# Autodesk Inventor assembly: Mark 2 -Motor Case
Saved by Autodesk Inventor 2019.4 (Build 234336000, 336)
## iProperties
Created: 2020-06
Part Number: Mark 2 -Motor Case
Document SubType Name: Assembly
Designer: Administrator
Title: Mark 2 -Motor Case v6
Author: Administrator
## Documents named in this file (5)
- c:\worker\convert-fusion-r04\tmp\job-1\983\output\files\42c61335-c52f-4d6a-bf4c-243a0625ae02\e151aba5-5efe-49e8-a742-b3bab9d02d3a.iam
- c:\worker\convert-fusion-r04\tmp\job-1\983\output\files\42c61335-c52f-4d6a-bf4c-243a0625ae02\Motor v5.ipt
- c:\worker\convert-fusion-r04\tmp\job-1\983\output\files\42c61335-c52f-4d6a-bf4c-243a0625ae02\Upgraded Screw Harry Edited v15.ipt
- c:\worker\convert-fusion-r04\tmp\job-1\983\output\files\42c61335-c52f-4d6a-bf4c-243a0625ae02\Upgraded Screw Harry Edited_Main Body Right v2.ipt
- c:\worker\convert-fusion-r04\tmp\job-1\983\output\files\42c61335-c52f-4d6a-bf4c-243a0625ae02\Component2.ipt
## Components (13 placed, 4 different names)
1. Motor v5:1
2. Motor v5:2
3. Motor v5:3
4. Motor v5:4
5. Motor v5:5
6. Motor v5:6
7. Upgraded Screw Harry Edited v15:1
8. Upgraded Screw Harry Edited v15:2
9. Upgraded Screw Harry Edited v15:3
10. Upgraded Screw Harry Edited_Main Body Right v2:1
11. Upgraded Screw Harry Edited_Main Body Right v2:2
12. Upgraded Screw Harry Edited_Main Body Right v2:3
13. Component2:1
